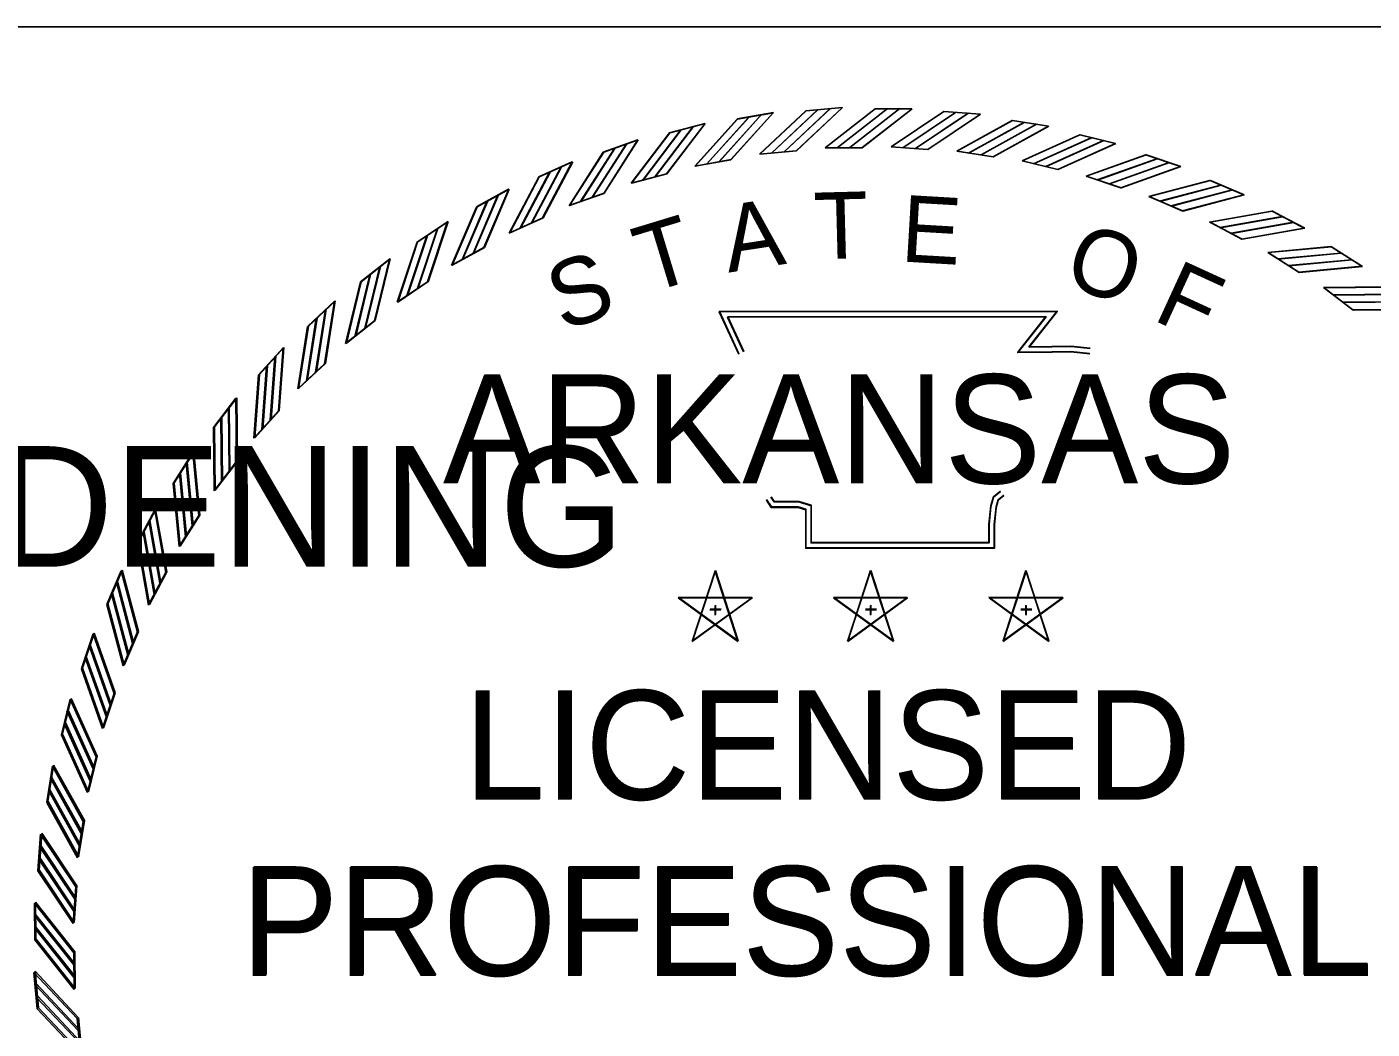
# Model space of a CAD drawing. Extents: x 0 to 1228740, y 0 to 152440.
# Drawn here: x 30.798 to 32.804, y 18.648 to 20.143 of the extents above; entities that cross this region are included whole.
import ezdxf

# ---------------------------------------------------------------- set-up
doc = ezdxf.new("R2010")
doc.units = 0
for name, color, linetype in [('R_Border', 7, 'Continuous'), ('R_XS_EARTHWORK_STAGE1', 7, 'Continuous'), ('STAMP', 7, 'Continuous'), ('STAMP_SWB', 7, 'Continuous')]:
    doc.layers.add(name, color=color, linetype=linetype)

msp = doc.modelspace()

# ---------------------------------------------------------------- linework, layer by layer
at = {"layer": 'R_Border'}
msp.add_line((29.1131, 20.1432), (33.4231, 20.1432), dxfattribs=at)
at = {"layer": 'STAMP'}
for p, q in [((31.8578, 20.0057), (31.9116, 20.0152)), ((31.96, 20.0179), (32.0144, 20.0229)), ((32.0634, 20.021), (32.118, 20.021)), ((32.1657, 20.017), (32.2202, 20.0129)), ((32.1657, 20.0169), (32.2201, 20.0129)), ((31.757, 19.9851), (31.8098, 19.999)), ((32.2678, 20.0036), (32.3217, 19.9951)), ((31.6582, 19.9563), (31.7097, 19.9745)), ((32.0871, 19.9644), (32.1417, 19.9604)), ((32.0871, 19.9644), (32.1417, 19.9604)), ((32.3684, 19.982), (32.4214, 19.9691)), ((31.7945, 19.9356), (31.8484, 19.9451)), ((31.8912, 19.9532), (31.9457, 19.9583)), ((31.9889, 19.9629), (32.0436, 19.9629)), ((32.1851, 19.9578), (32.2392, 19.9493)), ((32.4669, 19.9521), (32.5187, 19.9349)), ((31.5621, 19.9193), (31.6119, 19.9417)), ((31.6997, 19.91), (31.7526, 19.9239)), ((32.2822, 19.9432), (32.3354, 19.9302)), ((32.3778, 19.9205), (32.4297, 19.9033)), ((32.5626, 19.9142), (32.6128, 19.8928)), ((31.4694, 19.8746), (31.5172, 19.901)), ((31.6073, 19.8766), (31.6589, 19.8949)), ((32.4712, 19.8901), (32.5215, 19.8686)), ((32.6548, 19.8686), (32.703, 19.843)), ((31.3808, 19.8224), (31.4262, 19.8527)), ((31.518, 19.8358), (31.5679, 19.8582)), ((32.5618, 19.8521), (32.6101, 19.8265)), ((31.4324, 19.7877), (31.4803, 19.8142)), ((32.6489, 19.8067), (32.6949, 19.7772)), ((32.7429, 19.8154), (32.7889, 19.786)), ((31.2967, 19.763), (31.3395, 19.7969)), ((31.351, 19.7327), (31.3965, 19.7631)), ((32.7319, 19.7542), (32.7754, 19.721)), ((31.2178, 19.6969), (31.2576, 19.7342)), ((31.2744, 19.6712), (31.3173, 19.7052)), ((31.1447, 19.6245), (31.1813, 19.665)), ((31.2032, 19.6035), (31.2431, 19.641)), ((31.0778, 19.5463), (31.1109, 19.5897)), ((31.1378, 19.5302), (31.1745, 19.5708)), ((31.0175, 19.4628), (31.047, 19.5088)), ((31.0787, 19.4518), (31.1119, 19.4953)), ((30.9644, 19.3747), (30.9899, 19.4229)), ((31.0263, 19.3687), (31.0558, 19.4148)), ((30.9187, 19.2824), (30.9402, 19.3326)), ((30.9809, 19.2816), (31.0065, 19.33)), ((31.8248, 19.3321), (31.7907, 19.2273)), ((31.8589, 19.2273), (31.8249, 19.3322)), ((32.0564, 19.3321), (32.0223, 19.2273)), ((32.0905, 19.2273), (32.0565, 19.3322)), ((32.288, 19.3321), (32.2539, 19.2273)), ((32.322, 19.2273), (32.2881, 19.3322)), ((31.8799, 19.2921), (31.7697, 19.2922)), ((31.7698, 19.2921), (31.8589, 19.2272)), ((31.7908, 19.2273), (31.88, 19.2921)), ((32.1115, 19.2921), (32.0013, 19.2922)), ((32.0014, 19.2921), (32.0905, 19.2272)), ((32.0224, 19.2273), (32.1116, 19.2921)), ((32.3431, 19.2921), (32.2329, 19.2922)), ((32.233, 19.2921), (32.3221, 19.2272)), ((32.254, 19.2273), (32.3432, 19.2921)), ((31.817, 19.2745), (31.8334, 19.2745)), ((31.8249, 19.2804), (31.8249, 19.2665)), ((32.0486, 19.2745), (32.065, 19.2745)), ((32.0565, 19.2804), (32.0565, 19.2665)), ((32.2802, 19.2745), (32.2966, 19.2745)), ((32.2881, 19.2804), (32.2881, 19.2665)), ((30.8808, 19.1868), (30.8981, 19.2386)), ((30.9428, 19.1911), (30.9644, 19.2414)), ((30.8509, 19.0883), (30.8639, 19.1413)), ((30.9124, 19.0977), (30.9297, 19.1496)), ((30.8293, 18.9876), (30.8378, 19.0416)), ((30.8898, 19.0021), (30.9027, 19.0553)), ((30.8751, 18.905), (30.8836, 18.9591)), ((30.8161, 18.8856), (30.8201, 18.94)), ((30.8685, 18.807), (30.8726, 18.8616)), ((30.8113, 18.7828), (30.8108, 18.8374)), ((30.8701, 18.7088), (30.8696, 18.7635)), ((30.815, 18.6799), (30.81, 18.7343)), ((30.8797, 18.6111), (30.8747, 18.6655))]:
    msp.add_line(p, q, dxfattribs=at)
for points in [[(31.7945, 19.9355), (31.8578, 20.0057)], [(31.8118, 19.9384), (31.8751, 20.0086)], [(31.8304, 19.9421), (31.8937, 20.0123)], [(31.8484, 19.9451), (31.9116, 20.0153)], [(31.8911, 19.9532), (31.96, 20.0179)], [(31.9086, 19.9546), (31.9775, 20.0193)], [(31.9275, 19.9568), (31.9963, 20.0215)], [(31.9456, 19.9583), (32.0144, 20.023)], [(31.9888, 19.9628), (32.0633, 20.0209)], [(32.0064, 19.9627), (32.0809, 20.0208)], [(32.0254, 19.9631), (32.0999, 20.0212)], [(32.0436, 19.9629), (32.1181, 20.021)], [(32.087, 19.9644), (32.1656, 20.0169)], [(32.0871, 19.9644), (32.1656, 20.0168)], [(32.1045, 19.9629), (32.1832, 20.0155)], [(32.1046, 19.9629), (32.1831, 20.0154)], [(32.1235, 19.9619), (32.2021, 20.0145)], [(32.1235, 19.9619), (32.2021, 20.0144)], [(32.1416, 19.9604), (32.2203, 20.013)], [(32.1416, 19.9604), (32.2202, 20.0129)], [(31.6997, 19.9099), (31.7569, 19.985)], [(31.7167, 19.9142), (31.774, 19.9894)], [(31.7349, 19.9195), (31.7922, 19.9946)], [(31.7526, 19.9239), (31.8098, 19.9991)], [(32.185, 19.9578), (32.2677, 20.0036)], [(32.2024, 19.9549), (32.285, 20.0007)], [(32.2212, 19.9524), (32.3038, 19.9982)], [(32.2391, 19.9494), (32.3217, 19.9952)], [(31.6416, 19.889), (31.6925, 19.9686)], [(31.6589, 19.8949), (31.7097, 19.9745)], [(32.2822, 19.9431), (32.3683, 19.982)], [(32.2992, 19.9388), (32.3853, 19.9777)], [(32.3177, 19.9347), (32.4039, 19.9736)], [(32.3354, 19.9303), (32.4215, 19.9691)], [(31.6073, 19.8766), (31.6582, 19.9562)], [(31.6239, 19.8823), (31.6748, 19.9619)], [(32.3777, 19.9205), (32.4668, 19.9521)], [(32.3944, 19.9148), (32.4834, 19.9464)], [(31.5341, 19.8428), (31.5782, 19.9263)], [(31.5512, 19.8509), (31.5953, 19.9345)], [(31.5678, 19.8582), (31.612, 19.9418)], [(32.4125, 19.9092), (32.5015, 19.9408)], [(32.4297, 19.9033), (32.5187, 19.9349)], [(31.518, 19.8357), (31.5621, 19.9193)], [(32.4711, 19.8901), (32.5625, 19.9142)], [(32.4872, 19.883), (32.5786, 19.9071)], [(31.4642, 19.8055), (31.5013, 19.8924)], [(31.4802, 19.8142), (31.5172, 19.9011)], [(32.5048, 19.876), (32.5962, 19.9001)], [(32.5215, 19.8686), (32.6128, 19.8928)], [(31.4323, 19.7876), (31.4694, 19.8745)], [(31.4478, 19.796), (31.4849, 19.8829)], [(32.5617, 19.852), (32.6547, 19.8685)], [(31.3965, 19.763), (31.4262, 19.8527)], [(32.5771, 19.8437), (32.6702, 19.8602)], [(32.5941, 19.8352), (32.6871, 19.8517)], [(31.3657, 19.7422), (31.3954, 19.8319)], [(31.3812, 19.7531), (31.411, 19.8428)], [(32.6101, 19.8265), (32.7031, 19.843)], [(31.351, 19.7326), (31.3807, 19.8223)], [(32.6488, 19.8067), (32.7428, 19.8154)], [(32.6635, 19.797), (32.7576, 19.8058)], [(31.3029, 19.694), (31.3251, 19.7858)], [(31.3172, 19.7052), (31.3395, 19.797)], [(32.6797, 19.7872), (32.7737, 19.7959)], [(32.6949, 19.7772), (32.789, 19.786)], [(31.2883, 19.6819), (31.3105, 19.7737)], [(31.2744, 19.6711), (31.2967, 19.7629)], [(32.7318, 19.7542), (32.8263, 19.7552)], [(32.7457, 19.7434), (32.8402, 19.7444)], [(31.2431, 19.6409), (31.2577, 19.7343)], [(32.761, 19.7323), (32.8555, 19.7332)], [(31.2161, 19.6153), (31.2307, 19.7087)], [(31.2297, 19.6286), (31.2443, 19.722)], [(31.86, 19.6556), (31.8309, 19.7186), (32.3345, 19.7189), (32.2924, 19.666), (32.3266, 19.6665), (32.3552, 19.6668), (32.3837, 19.6637)], [(31.8672, 19.6589), (31.8434, 19.7106), (32.3179, 19.7109), (32.2757, 19.6578), (32.3267, 19.6585), (32.3548, 19.6588), (32.3828, 19.6558)], [(32.7754, 19.7211), (32.8698, 19.722)], [(31.2032, 19.6034), (31.2178, 19.6968)], [(31.1744, 19.5708), (31.1813, 19.665)], [(31.1621, 19.5574), (31.169, 19.6517)], [(31.1378, 19.5302), (31.1447, 19.6244)], [(31.1497, 19.5431), (31.1566, 19.6373)], [(31.1119, 19.4953), (31.1109, 19.5897)], [(31.1007, 19.4809), (31.0997, 19.5754)], [(31.0787, 19.4517), (31.0778, 19.5462)], [(31.0895, 19.4656), (31.0885, 19.56)], [(31.0557, 19.4148), (31.047, 19.5089)], [(31.0458, 19.3996), (31.037, 19.4936)], [(31.0263, 19.3687), (31.0175, 19.4627)], [(31.0359, 19.3834), (31.0271, 19.4774)], [(32.2551, 19.4445), (32.2465, 19.4375), (32.2437, 19.4271), (32.2408, 19.401), (32.2408, 19.3662), (31.9597, 19.3662), (31.9597, 19.4132), (31.9597, 19.4236), (31.9483, 19.4271), (31.9083, 19.4271), (31.9012, 19.4379)], [(32.2501, 19.4507), (32.2395, 19.4421), (32.2358, 19.4286), (32.2328, 19.4014), (32.2328, 19.3742), (31.9677, 19.3742), (31.9677, 19.4132), (31.9677, 19.4295), (31.9495, 19.4351), (31.9126, 19.4351), (31.9079, 19.4423)], [(31.0064, 19.33), (30.9899, 19.423)], [(30.9978, 19.314), (30.9813, 19.407)], [(30.9893, 19.297), (30.9728, 19.39)], [(30.9809, 19.2816), (30.9644, 19.3746)], [(30.9643, 19.2414), (30.9402, 19.3327)], [(30.957, 19.2247), (30.9329, 19.316)], [(30.9429, 19.191), (30.9187, 19.2824)], [(30.9499, 19.2071), (30.9258, 19.2984)], [(30.9296, 19.1496), (30.898, 19.2386)], [(30.9181, 19.1142), (30.8865, 19.2033)], [(30.9237, 19.1324), (30.8921, 19.2214)], [(30.9124, 19.0976), (30.8808, 19.1867)], [(30.9027, 19.0552), (30.8638, 19.1414)], [(30.8982, 19.0376), (30.8594, 19.1237)], [(30.8941, 19.0191), (30.8553, 19.1052)], [(30.8898, 19.0021), (30.851, 19.0882)], [(30.8836, 18.959), (30.8378, 19.0416)], [(30.8806, 18.9411), (30.8348, 19.0237)], [(30.8781, 18.9223), (30.8322, 19.0049)], [(30.8752, 18.9049), (30.8294, 18.9876)], [(30.871, 18.8434), (30.8185, 18.922)], [(30.8725, 18.8615), (30.82, 18.9401)], [(30.87, 18.8245), (30.8176, 18.903)], [(30.8686, 18.8069), (30.8161, 18.8855)], [(30.8695, 18.7635), (30.8107, 18.8374)], [(30.8695, 18.7453), (30.8107, 18.8192)], [(30.8701, 18.7263), (30.8113, 18.8003)], [(30.8701, 18.7087), (30.8113, 18.7827)], [(30.8746, 18.6655), (30.81, 18.7343)], [(30.8761, 18.6474), (30.8115, 18.7162)], [(30.8783, 18.6285), (30.8136, 18.6974)], [(30.8798, 18.611), (30.8151, 18.6798)]]:
    msp.add_lwpolyline(points, dxfattribs=at)
at = {"layer": 'STAMP_SWB'}
for p, q in [((31.8575, 20.0058), (31.9113, 20.0153)), ((31.9598, 20.018), (32.0143, 20.023)), ((32.0633, 20.021), (32.118, 20.021)), ((32.1657, 20.017), (32.2202, 20.0129)), ((32.1657, 20.0169), (32.2203, 20.0129)), ((31.7565, 19.9851), (31.8094, 19.999)), ((32.2679, 20.0037), (32.3219, 19.9952)), ((31.6576, 19.9562), (31.7091, 19.9745)), ((32.0871, 19.9644), (32.1417, 19.9604)), ((32.0871, 19.9644), (32.1417, 19.9604)), ((32.3687, 19.982), (32.4218, 19.9691)), ((31.7941, 19.9355), (31.8481, 19.945)), ((31.8909, 19.9532), (31.9454, 19.9582)), ((31.9887, 19.9629), (32.0435, 19.9629)), ((32.1852, 19.9578), (32.2393, 19.9493)), ((32.4673, 19.9521), (32.5192, 19.9348)), ((31.5614, 19.9193), (31.6113, 19.9417)), ((31.6992, 19.9099), (31.7522, 19.9238)), ((32.2824, 19.9431), (32.3357, 19.9302)), ((32.3781, 19.9205), (32.4301, 19.9032)), ((32.5631, 19.9142), (32.6134, 19.8927)), ((31.4686, 19.8745), (31.5164, 19.9009)), ((31.6067, 19.8765), (31.6583, 19.8948)), ((32.4716, 19.89), (32.522, 19.8685)), ((32.6555, 19.8684), (32.7038, 19.8428)), ((31.3798, 19.8222), (31.4253, 19.8525)), ((31.5172, 19.8356), (31.5672, 19.8581)), ((32.5623, 19.8519), (32.6107, 19.8263)), ((31.4315, 19.7875), (31.4794, 19.814)), ((32.6495, 19.8065), (32.6957, 19.7769)), ((32.7437, 19.8152), (32.7898, 19.7857)), ((31.2956, 19.7627), (31.3385, 19.7967)), ((31.35, 19.7324), (31.3956, 19.7628)), ((32.7327, 19.754), (32.7762, 19.7207)), ((31.2167, 19.6965), (31.2565, 19.7339)), ((31.2733, 19.6708), (31.3163, 19.7048)), ((31.1434, 19.624), (31.1801, 19.6646)), ((31.202, 19.6031), (31.242, 19.6405)), ((31.0764, 19.5457), (31.1096, 19.5892)), ((31.1366, 19.5297), (31.1733, 19.5703)), ((31.0161, 19.4622), (31.0456, 19.5082)), ((31.0774, 19.4511), (31.1106, 19.4947)), ((30.9629, 19.3739), (30.9885, 19.4222)), ((31.0249, 19.368), (31.0544, 19.4141)), ((30.9172, 19.2816), (30.9387, 19.3318)), ((30.9794, 19.2808), (31.005, 19.3292)), ((31.8244, 19.3313), (31.7902, 19.2263)), ((31.8585, 19.2264), (31.8245, 19.3314)), ((32.0563, 19.3313), (32.0221, 19.2263)), ((32.0904, 19.2264), (32.0564, 19.3314)), ((32.2882, 19.3313), (32.254, 19.2263)), ((32.3223, 19.2264), (32.2883, 19.3314)), ((31.8796, 19.2912), (31.7692, 19.2913)), ((31.7693, 19.2912), (31.8585, 19.2263)), ((31.7904, 19.2264), (31.8797, 19.2912)), ((32.1115, 19.2912), (32.0011, 19.2913)), ((32.0012, 19.2912), (32.0904, 19.2263)), ((32.0223, 19.2264), (32.1116, 19.2912)), ((32.3434, 19.2912), (32.233, 19.2913)), ((32.2331, 19.2912), (32.3223, 19.2263)), ((32.2541, 19.2264), (32.3435, 19.2912)), ((31.8166, 19.2736), (31.833, 19.2736)), ((31.8245, 19.2795), (31.8245, 19.2656)), ((32.0485, 19.2736), (32.0649, 19.2736)), ((32.0564, 19.2795), (32.0564, 19.2656)), ((32.2804, 19.2736), (32.2968, 19.2736)), ((32.2883, 19.2795), (32.2883, 19.2656)), ((30.8792, 19.1857), (30.8965, 19.2376)), ((30.9413, 19.1901), (30.9629, 19.2405)), ((30.9108, 19.0966), (30.9282, 19.1486)), ((30.8493, 19.0871), (30.8622, 19.1402)), ((30.8882, 19.0009), (30.9011, 19.0541)), ((30.8276, 18.9864), (30.8361, 19.0404)), ((30.8735, 18.9036), (30.882, 18.9578)), ((30.8144, 18.8842), (30.8184, 18.9387)), ((30.8669, 18.8055), (30.8709, 18.8602)), ((30.8096, 18.7812), (30.8091, 18.8359)), ((30.8685, 18.7072), (30.8679, 18.762)), ((30.8133, 18.6783), (30.8083, 18.7327)), ((30.8781, 18.6093), (30.8731, 18.6639))]:
    msp.add_line(p, q, dxfattribs=at)
for points in [[(31.7941, 19.9355), (31.8574, 20.0057)], [(31.8114, 19.9384), (31.8748, 20.0086)], [(31.8301, 19.9421), (31.8934, 20.0123)], [(31.848, 19.9451), (31.9114, 20.0153)], [(31.8908, 19.9532), (31.9597, 20.0179)], [(31.9083, 19.9546), (31.9773, 20.0194)], [(31.9272, 19.9568), (31.9961, 20.0215)], [(31.9454, 19.9583), (32.0143, 20.0231)], [(31.9887, 19.9628), (32.0633, 20.021)], [(32.0063, 19.9627), (32.0809, 20.0208)], [(32.0253, 19.9631), (32.0998, 20.0212)], [(32.0435, 19.9629), (32.1181, 20.0211)], [(32.087, 19.9644), (32.1656, 20.0169)], [(32.087, 19.9644), (32.1657, 20.0169)], [(32.1045, 19.9629), (32.1832, 20.0155)], [(32.1045, 19.9629), (32.1832, 20.0154)], [(32.1235, 19.9619), (32.2021, 20.0145)], [(32.1235, 19.9619), (32.2022, 20.0145)], [(32.1416, 19.9604), (32.2203, 20.013)], [(32.1417, 19.9604), (32.2203, 20.013)], [(31.6991, 19.9098), (31.7565, 19.9851)], [(31.7162, 19.9141), (31.7735, 19.9894)], [(31.7344, 19.9194), (31.7918, 19.9946)], [(31.7521, 19.9239), (31.8094, 19.9991)], [(32.1851, 19.9578), (32.2679, 20.0036)], [(32.2025, 19.9549), (32.2852, 20.0007)], [(32.2213, 19.9523), (32.304, 19.9982)], [(32.2393, 19.9493), (32.322, 19.9952)], [(31.641, 19.8889), (31.692, 19.9686)], [(31.6583, 19.8948), (31.7092, 19.9745)], [(32.2824, 19.9431), (32.3686, 19.982)], [(32.2994, 19.9388), (32.3857, 19.9777)], [(32.318, 19.9347), (32.4042, 19.9736)], [(32.3356, 19.9302), (32.4219, 19.9691)], [(31.6066, 19.8764), (31.6575, 19.9562)], [(31.6233, 19.8822), (31.6742, 19.9619)], [(32.3781, 19.9205), (32.4672, 19.9521)], [(32.3947, 19.9147), (32.4839, 19.9464)], [(31.5333, 19.8426), (31.5775, 19.9263)], [(31.5505, 19.8508), (31.5946, 19.9344)], [(31.5671, 19.8581), (31.6113, 19.9417)], [(32.4129, 19.9091), (32.502, 19.9408)], [(32.4301, 19.9032), (32.5192, 19.9348)], [(31.5172, 19.8355), (31.5614, 19.9192)], [(32.4716, 19.89), (32.563, 19.9141)], [(32.4877, 19.8829), (32.5791, 19.9071)], [(31.4633, 19.8053), (31.5004, 19.8923)], [(31.4794, 19.814), (31.5165, 19.901)], [(32.5053, 19.8758), (32.5968, 19.9)], [(32.522, 19.8685), (32.6134, 19.8927)], [(31.4314, 19.7874), (31.4686, 19.8744)], [(31.4469, 19.7958), (31.484, 19.8828)], [(32.5622, 19.8519), (32.6554, 19.8684)], [(31.3955, 19.7628), (31.4253, 19.8526)], [(32.5777, 19.8435), (32.6708, 19.86)], [(32.5947, 19.835), (32.6878, 19.8515)], [(31.3647, 19.7419), (31.3945, 19.8317)], [(31.3803, 19.7528), (31.4101, 19.8426)], [(32.6107, 19.8263), (32.7038, 19.8429)], [(31.35, 19.7323), (31.3798, 19.8221)], [(32.6494, 19.8064), (32.7436, 19.8152)], [(32.6642, 19.7968), (32.7584, 19.8056)], [(31.3018, 19.6936), (31.3241, 19.7856)], [(31.3162, 19.7048), (31.3385, 19.7968)], [(32.6804, 19.7869), (32.7746, 19.7957)], [(32.6956, 19.777), (32.7898, 19.7857)], [(31.2872, 19.6815), (31.3095, 19.7734)], [(31.2733, 19.6707), (31.2956, 19.7626)], [(32.7326, 19.754), (32.8272, 19.7549)], [(32.7465, 19.7431), (32.8411, 19.7441)], [(31.2419, 19.6405), (31.2565, 19.734)], [(32.7618, 19.732), (32.8564, 19.7329)], [(31.215, 19.6149), (31.2296, 19.7084)], [(31.2285, 19.6282), (31.2431, 19.7216)], [(31.8597, 19.6551), (31.8305, 19.7183), (32.3347, 19.7186), (32.2926, 19.6656), (32.3268, 19.6661), (32.3555, 19.6664), (32.384, 19.6633)], [(31.8669, 19.6585), (31.843, 19.7103), (32.3181, 19.7106), (32.2759, 19.6574), (32.3269, 19.6581), (32.3551, 19.6584), (32.3832, 19.6554)], [(32.7762, 19.7208), (32.8708, 19.7217)], [(31.202, 19.603), (31.2166, 19.6964)], [(31.1732, 19.5703), (31.1801, 19.6647)], [(31.1609, 19.5569), (31.1677, 19.6513)], [(31.1365, 19.5296), (31.1434, 19.6239)], [(31.1485, 19.5425), (31.1553, 19.6369)], [(31.1106, 19.4947), (31.1096, 19.5892)], [(31.0994, 19.4803), (31.0984, 19.5749)], [(31.0774, 19.451), (31.0764, 19.5456)], [(31.0882, 19.4649), (31.0872, 19.5595)], [(31.0543, 19.4141), (31.0456, 19.5083)], [(31.0444, 19.3988), (31.0356, 19.493)], [(31.0345, 19.3826), (31.0257, 19.4768)], [(31.0249, 19.3679), (31.0161, 19.4621)], [(32.2553, 19.4439), (32.2467, 19.4369), (32.2438, 19.4264), (32.241, 19.4003), (32.241, 19.3654), (31.9595, 19.3654), (31.9595, 19.4125), (31.9595, 19.4229), (31.9481, 19.4264), (31.908, 19.4264), (31.9009, 19.4373)], [(32.2502, 19.45), (32.2396, 19.4414), (32.2359, 19.4279), (32.233, 19.4007), (32.233, 19.3734), (31.9675, 19.3734), (31.9675, 19.4125), (31.9675, 19.4288), (31.9493, 19.4344), (31.9124, 19.4344), (31.9076, 19.4416)], [(31.005, 19.3291), (30.9885, 19.4223)], [(30.9963, 19.3131), (30.9798, 19.4063)], [(30.9878, 19.2962), (30.9713, 19.3893)], [(30.9794, 19.2807), (30.9629, 19.3738)], [(30.9628, 19.2404), (30.9387, 19.3319)], [(30.9555, 19.2237), (30.9313, 19.3152)], [(30.9484, 19.2061), (30.9243, 19.2976)], [(30.9413, 19.19), (30.9172, 19.2815)], [(30.9281, 19.1485), (30.8965, 19.2377)], [(30.9166, 19.1132), (30.885, 19.2023)], [(30.9222, 19.1313), (30.8906, 19.2205)], [(30.9109, 19.0965), (30.8792, 19.1857)], [(30.8966, 19.0364), (30.8577, 19.1227)], [(30.9011, 19.0541), (30.8622, 19.1403)], [(30.8925, 19.0179), (30.8537, 19.1041)], [(30.8882, 19.0008), (30.8493, 19.087)], [(30.879, 18.9397), (30.8331, 19.0225)], [(30.882, 18.9577), (30.8361, 19.0404)], [(30.8764, 18.9209), (30.8306, 19.0037)], [(30.8736, 18.9036), (30.8277, 18.9863)], [(30.8694, 18.842), (30.8169, 18.9206)], [(30.8709, 18.8601), (30.8184, 18.9388)], [(30.8684, 18.823), (30.8159, 18.9016)], [(30.867, 18.8054), (30.8144, 18.8841)], [(30.8679, 18.7619), (30.8091, 18.836)], [(30.8679, 18.7437), (30.8091, 18.8177)], [(30.8685, 18.7247), (30.8096, 18.7988)], [(30.8685, 18.7071), (30.8096, 18.7812)], [(30.873, 18.6638), (30.8083, 18.7327)], [(30.8745, 18.6457), (30.8098, 18.7146)], [(30.8767, 18.6268), (30.8119, 18.6957)], [(30.8782, 18.6092), (30.8134, 18.6782)]]:
    msp.add_lwpolyline(points, dxfattribs=at)

# ---------------------------------------------------------------- texts
at = {"layer": 'R_XS_EARTHWORK_STAGE1'}
msp.add_text('TEMP. WIDENING', height=0.18, dxfattribs=at).set_placement((29.657, 19.3378))
at = {"layer": 'STAMP'}
for s, height, rotation, p in [('T', 0.0995, 1.4789, (31.9727, 19.7963)), ('T', 0.0993, 1.4789, (31.9729, 19.7965)), ('E', 0.0993, 356.672, (32.1, 19.7935)), ('A', 0.0993, 8.6788, (31.8446, 19.7768)), ('T', 0.0993, 16.9015, (31.724, 19.7453)), ('O', 0.0993, 341.2218, (32.3412, 19.7595)), ('S', 0.0993, 19.7726, (31.5977, 19.6886)), ('F', 0.0993, 335.3628, (32.4751, 19.7071))]:
    msp.add_text(s, height=height, rotation=rotation, dxfattribs=at).set_placement(p)
for s, height, p in [('ARKANSAS', 0.16212, (31.4193, 19.4626)), ('LICENSED', 0.16212, (31.4501, 18.9914)), ('PROFESSIONAL', 0.162116, (31.1182, 18.729))]:
    msp.add_text(s, height=height, dxfattribs=at).set_placement(p)
at = {"layer": 'STAMP_SWB'}
for s, height, rotation, p in [('T', 0.0995, 1.4789, (31.9727, 19.7963)), ('T', 0.0995, 1.4789, (31.9727, 19.7963)), ('E', 0.0995, 356.672, (32.1, 19.7933)), ('A', 0.0995, 8.6788, (31.8443, 19.7765)), ('T', 0.0995, 16.9015, (31.7235, 19.745)), ('O', 0.0995, 341.2218, (32.3415, 19.7592)), ('S', 0.0995, 19.7726, (31.5971, 19.6882)), ('F', 0.0995, 335.3628, (32.4755, 19.7068)), ('ARKANSAS', 0.16232, 360, (31.4184, 19.462)), ('LICENSED', 0.16232, 360, (31.4493, 18.9902)), ('PROFESSIONAL', 0.162324, 360, (31.1169, 18.7274))]:
    msp.add_text(s, height=height, rotation=rotation, dxfattribs=at).set_placement(p)

doc.saveas('drawing.dxf')
